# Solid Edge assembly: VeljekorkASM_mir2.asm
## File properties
Author: KULL
Template: Iso Metric Assembly.asm
Last saved by: KULL
Revision: 2
Application: Solid Edge
Username: KULL
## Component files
rehvikork_mir2.par
rehvikork_logo_mir2.par
VeljekorkASM.asm
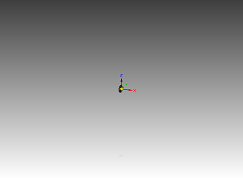
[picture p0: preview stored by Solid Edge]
